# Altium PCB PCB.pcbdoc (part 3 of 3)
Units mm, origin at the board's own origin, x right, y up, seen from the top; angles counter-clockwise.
Board outline 65.2 x 64.45 mm, 2 copper layers (Top Layer, Bottom Layer); 194 components, 135 nets, 803 pads, 401 vias.
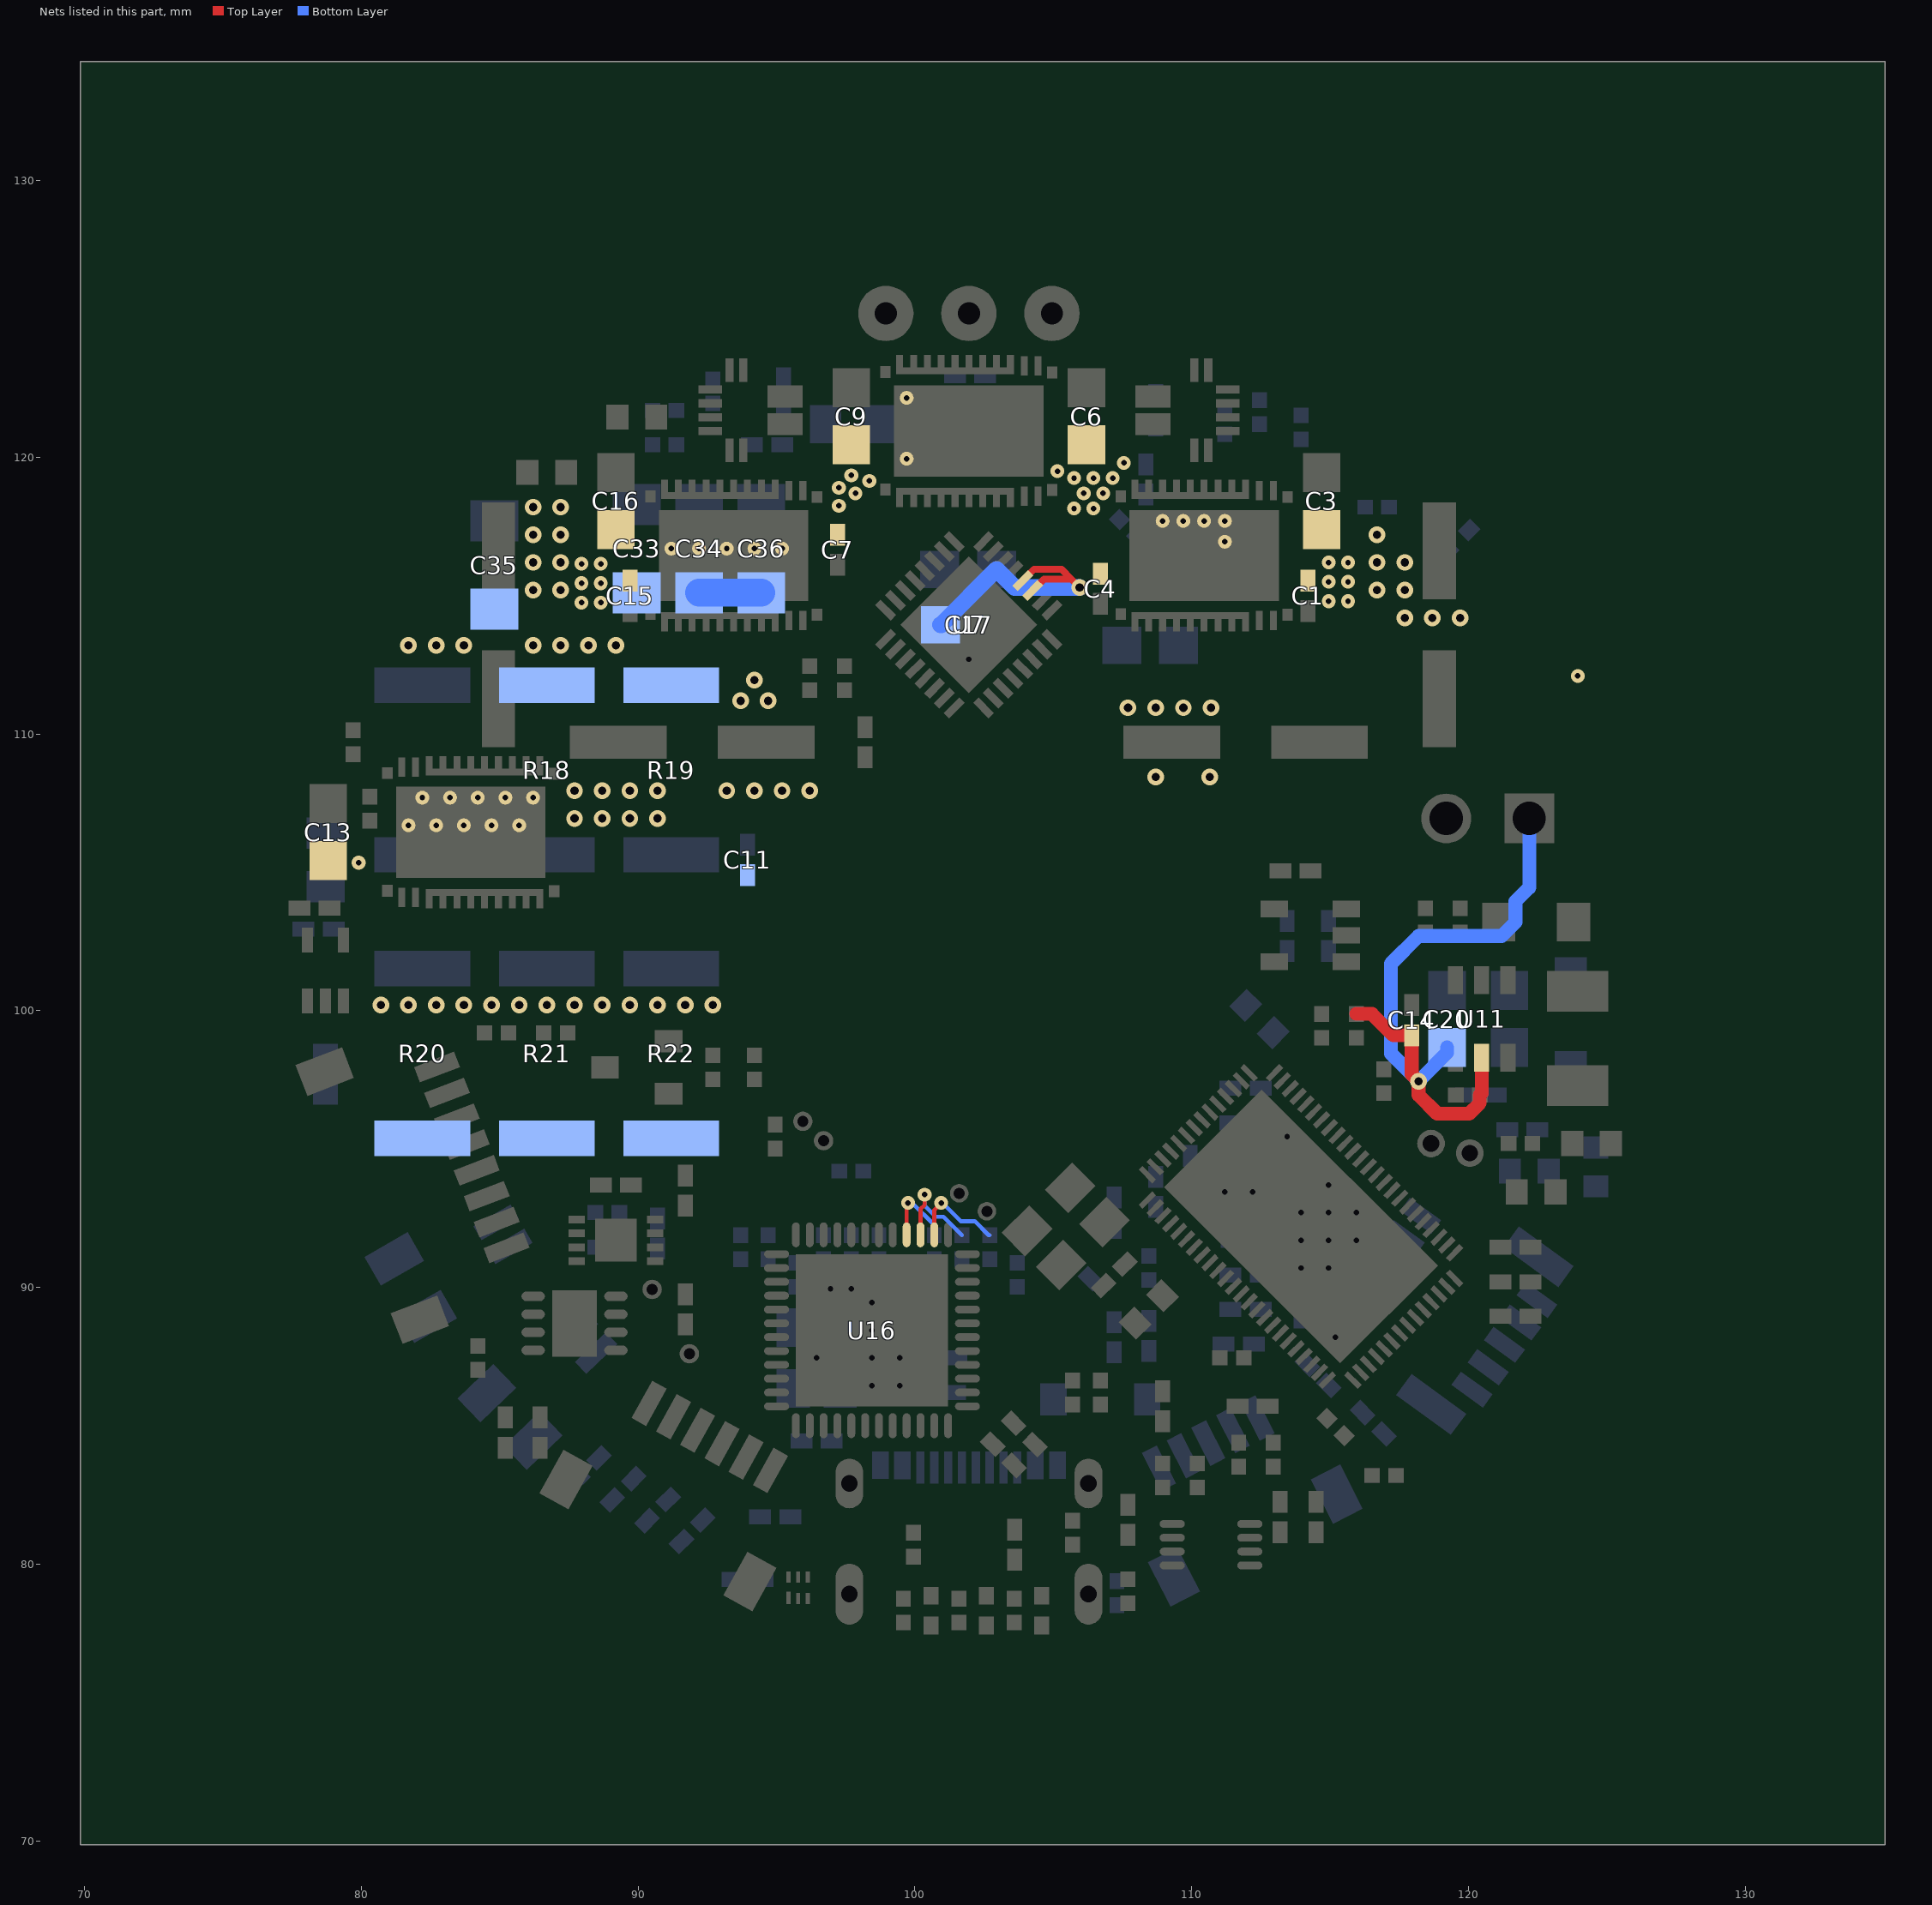
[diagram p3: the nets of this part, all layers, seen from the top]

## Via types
v1: diameter 0.5, hole 0.2, Top Layer to Bottom Layer, 297 vias
v2: diameter 0.6, hole 0.3, Top Layer to Bottom Layer, 104 vias

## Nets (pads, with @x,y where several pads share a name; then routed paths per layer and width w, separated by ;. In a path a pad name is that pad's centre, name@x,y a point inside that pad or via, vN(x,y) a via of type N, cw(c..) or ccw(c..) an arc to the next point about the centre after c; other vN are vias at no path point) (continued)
V: C1.1 C3.1 C4.1 C6.1 C7.1 C9.1 C11.1 C13.1 C14.1 C15.1 C16.1 C17.1 C20.1 C33.1 C34.1 C35.1 C36.1 pad.1@81.7,106.7 pad.1@82.2,107.7 pad.1@82.7,106.7 pad.1@83.2,107.7 pad.1@83.7,106.7 pad.1@84.2,107.7 pad.1@84.7,106.7 pad.1@85.2,107.7 pad.1@85.7,106.7 pad.1@86.2,107.7 pad.1@91.2,116.7 pad.1@92.2,116.7 pad.1@93.2,116.7 pad.1@94.2,116.7 pad.1@95.2,116.7 pad.1@99.7,119.95 pad.1@99.7,122.15 pad.1@108.95,117.7 pad.1@109.7,117.7 pad.1@110.45,117.7 pad.1@111.2,116.95 pad.1@111.2,117.7 R18.1 R19.1 R20.1 R21.1 R22.1 U7.3 U7.4 U11.5 | length 36.7
  Top Layer w0.25: U7.4@103.895,115.541 104.304,115.95 105.3,115.95 105.65,115.6 ; U7.3@104.248,115.187 104.661,115.6 105.65,115.6 ; v2(105.95,115.3) 105.65,115.6
  Top Layer w0.5: 115.95,99.883 116.517,99.883 117.29,99.11 C14.1@117.95,99.11 117.95,97.7 v2(118.2,97.45) 118.2,96.95 118.872,96.278 120.028,96.278 120.412,96.662 120.412,96.95 120.48,97.017 U11.5@120.48,98.3
  Bottom Layer w0.5: C20.1@119.23,98.67 119.23,98.48 v2(118.2,97.45) 117.2,98.45 117.2,101.7 118.2,102.7 121.2,102.7 121.7,103.2 121.7,103.95 122.2,104.45 122.2,106.95
  Bottom Layer w0.6: C17.1@100.92,113.95 100.95,113.95 102.95,115.95 103.6,115.3 v2(105.95,115.3)
  Bottom Layer w1: C34.1@92.2,115.107 C36.1@94.45,115.107
  other v1: 79.9,105.35 123.95,112.1 87.95,114.75 88.65,114.75 114.95,114.8 115.65,114.8 87.95,115.45 88.65,115.45 114.95,115.5 115.65,115.5 87.95,116.15 88.65,116.15 114.95,116.2 115.65,116.2 105.75,118.15 106.45,118.15 97.25,118.25 97.85,118.7 106.1,118.7 106.8,118.7 97.25,118.9 98.35,119.15 105.75,119.25 106.45,119.25 107.15,119.25 97.7,119.35 105.15,119.5 107.55,119.8
  other v2: 80.7,100.2 81.7,100.2 82.7,100.2 83.7,100.2 84.7,100.2 85.7,100.2 86.7,100.2 87.7,100.2 88.7,100.2 89.7,100.2 90.7,100.2 91.7,100.2 92.7,100.2 87.7,106.95 88.7,106.95 89.7,106.95 90.7,106.95 87.7,107.95 88.7,107.95 89.7,107.95 90.7,107.95 93.2,107.95 94.2,107.95 95.2,107.95 96.2,107.95 108.7,108.45 110.65,108.45 107.7,110.95 108.7,110.95 109.7,110.95 110.7,110.95 93.7,111.2 94.7,111.2 94.2,111.95 81.7,113.2 82.7,113.2 83.7,113.2 86.2,113.2 87.2,113.2 88.2,113.2 89.2,113.2 117.7,114.2 118.7,114.2 119.7,114.2 86.2,115.2 87.2,115.2 116.7,115.2 117.7,115.2 86.2,116.2 87.2,116.2 116.7,116.2 117.7,116.2 86.2,117.2 87.2,117.2 116.7,117.2 86.2,118.2 87.2,118.2
VDS_0: U16.38 | length 3.5
  Top Layer w0.15: U16.38@100.7,91.899 100.7,92.8 v1(100.95,93.05)
  Bottom Layer w0.15: v1@100.95,92.95 v1(100.95,93.05) ; v1@101,93.05 101.657,92.393 102.157,92.393 102.667,91.883 102.7,91.883
VDS_18: U16.39 | length 3.7
  Top Layer w0.15: U16.39@100.2,91.899 100.2,92.825 100.35,92.975 v1(100.35,93.35)
  Bottom Layer w0.15: v1(100.35,93.35) 100.35,92.95 100.75,92.55 101.033,92.55 101.7,91.883
VDS_75: U16.40 | length 2.8
  Top Layer w0.15: U16.40@99.7,91.899 99.7,93 v1(99.75,93.05)
  Bottom Layer w0.15: v1(99.75,93.05) 99.9,93.05 100.7,92.25 100.7,91.883
"": 
pads on no net: C1.2 C2.2 C3.2 C4.2 C5.2 C6.2 C7.2 C8.2 C9.2 C10.2 C11.2 C12.2 C13.2 C14.2 C15.2 C16.2 C17.2 C18.2 C19.2 C20.2 C21.2 C22.2 C23.2 C24.2 C25.1 C26.1 C27.1 C28.1 C29.1 C30.2 C31.2 C32.2 C33.2 C34.2 C35.2 C36.2 C37.2 C38.2 C39.2 C40.2 C41.2 C42.2 C43.2 C44.2 C45.2 C46.2 C47.2 C48.2 C49.2 C50.2 C51.2 C52.2 C53.2 C54.2 C55.2 C56.2 C57.2 C58.2 C59.2 C60.2 C61.2 C62.2 C63.2 C64.2 C65.2 C66.2 C67.2 C68.2 C69.2 C70.2 C71.2 C72.2 C73.2 C74.2 C75.2 C76.2 C77.2 C78.2 C79.2 C80.2 C81.2 C82.2 C83.2 C84.2 C85.2 C86.2 C87.2 C88.2 C89.2 C90.2 C91.2 CAN.2 D1.2 D2.2 ENC.1 GRE.1 L1.2 LED1.2 LED2.2 LED3.2 LED4.1 Q1.2 R1.2 R2.2 R3.2 R4.2 R5.2 R6.2 R7.2 R8.2 R9.2 R10.2 R11.2 R12.2 R13.2 R14.2 R15.2 R16.2 R17.2 R18.2 R19.2 R20.2 R21.2 R22.2 R23.2 R24.2 R25.2 R26.2 R27.2 R28.2 R29.2 R30.2 R31.2 R32.2 R33.2 R34.2 R35.2 R36.2 R37.2 R38.2 R39.2 R40.2 R41.2 R42.2 R43.2 R44.2 R45.2 R46.2 R47.2 R48.2 R49.2 R50.2 R51.2 R52.2 R53.2 R54.2 R55.2 R56.2 R57.2 R58.2 R59.2 R60.2 R61.2 R62.2 R63.2 R64.2 R65.2 R66.2 R67.2 RS485.2 RTMI.1 RTMI.11 SPI.1 U1.21 U1.23 U1.24 U1.25 U1.26 U1.27 U2.21 U2.23 U2.24 U2.25 U2.26 U2.27 U3.21 U3.23 U3.24 U3.25 U3.26 U3.27 U4.12 U5.2 U5.21 U5.23 U5.24 U5.25 U5.26 U5.27 U6.1 U6.10 U6.11 U6.25 U6.26 U6.27 U6.28 U6.29 U6.30 U6.36 U6.37 U6.38 U6.48 U6.49 U6.56 U6.57 U6.58 U6.64 U6.65 U6.66 U6.67 U6.68 U6.69 U6.70 U6.71 U6.74 U7.33 U8.12 U9.1 U10.1 U10.5 U11.3 U13.5 U14.1 U15.1 U17.1 U18.6 USB.2 USB.3 USB.9 X1.1 X2.1

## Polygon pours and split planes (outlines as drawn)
V on Bottom Layer (solid, pour order 2): 114.7,114.55 115.9,114.55 115.9,116.45 114.7,116.45
GND on Top Layer (solid, pour order 3): 107.8,105.25 112.85,105.25 112.85,106.85 107.8,106.85
BR on Bottom Layer (solid, remove dead copper, pour order 4): 79.95,100.95 93.2,100.95 93.2,106.45 79.95,106.45
BR on Top Layer (solid, remove dead copper, pour order 5): 80.2,102.2 93.45,102.2 93.45,104.45 80.2,104.45
GND on Mid-Layer 1 (solid, remove dead copper, pour order 7): 76.7,105.7 127.7,105.7 127.7,127.2 76.7,127.2
V on Top Layer (solid, remove dead copper, pour order 15): 107.2,107.95 111.2,107.95 111.2,111.45 107.2,111.45
GND on Top Layer (solid, remove dead copper, pour order 17): 76.2,99.7 79.7,99.7 79.7,103.95 76.2,103.95
V on Top Layer (solid, remove dead copper, pour order 18): 76.2,99.7 97.2,99.7 97.2,107.2 76.2,107.2
V on Bottom Layer (solid, remove dead copper, pour order 19): 80.2,94.7 92.95,94.7 92.95,100.45 80.2,100.45
V on Bottom Layer (solid, remove dead copper, pour order 20): 79.95,110.45 93.2,110.45 93.2,116.45 79.95,116.45
GND on Top Layer (solid, remove dead copper, pour order 21): 76.2,105.7 128.7,105.7 128.7,127.95 76.2,127.95
GND on Bottom Layer (solid, remove dead copper, pour order 22): 76.2,105.7 128.7,105.7 128.7,127.95 76.2,127.95
V on Bottom Layer (solid, remove dead copper, pour order 23): 76.2,94.7 101.7,94.7 101.7,105.7 76.2,105.7
GND on Mid-Layer 1 (solid, pour order 24): 76.7,99.7 95.95,99.7 95.95,106.2 76.7,106.2
V on Bottom Layer (solid): 96.95,119.2 96.95,117.95 97.2,117.7 98.7,119.2 98.7,119.45 97.95,119.45 97.7,119.7 97.45,119.7
V on Bottom Layer (solid, pour order 1): 104.2,118.95 104.95,119.7 107.072,119.7 107.104,119.669 107.2,119.765 107.2,120.2 107.7,120.2 107.7,120.187 107.965,119.922 107.965,118.297 107.851,118.184 107.434,118.184 106.95,117.7 105.45,117.7 104.963,118.187 104.963,118.815 104.335,118.815
V on Mid-Layer 2 (solid, remove dead copper, pour order 6): 76.2,99.45 101.95,99.45 101.95,105.7 128.7,105.7 128.7,127.95 76.2,127.95
$3N73172 on Top Layer (solid, remove dead copper, pour order 8): 94.7,120.7 93.45,119.45 90.7,119.45 90.7,118.45 95.2,118.45 95.2,119.7 95.95,120.45 95.95,121.45 94.7,121.45
C on Top Layer (solid, remove dead copper, pour order 9): 94.7,121.95 94.7,123.95 97.45,126.7 100.2,126.7 100.2,124.7 97.45,121.95
B on Top Layer (solid, remove dead copper, pour order 10): 99.2,122.95 99.2,123.7 100.2,124.7 100.2,126.7 103.7,126.7 103.7,122.95
A on Top Layer (solid, remove dead copper, pour order 11): 109.2,121.95 109.2,123.2 105.7,126.7 103.7,126.7 103.7,122.95 106.95,122.95 107.95,121.95
$3N68599 on Top Layer (solid, remove dead copper, pour order 12): 107.95,121.45 107.95,118.45 112.2,118.45 112.2,119.45 110.45,119.45 109.2,120.7 109.2,121.45
V on Top Layer (solid, remove dead copper, pour order 13): 99.2,122.7 104.7,122.7 104.7,122.2 105.45,121.45 106.95,121.45 106.95,118.95 107.7,118.2 119.45,118.2 119.45,114.95 107.45,114.95 106.95,115.45 106.45,115.45 106.2,115.2 104.7,115.2 104.2,114.7 103.45,115.45 105.45,117.45 105.45,118.7 104.95,119.2 99.2,119.2 97.45,117.45 97.45,116.7 96.95,116.7 96.2,115.95 96.2,114.95 89.45,114.95 87.7,113.2 79.2,113.2 79.2,118.45 95.2,118.45 95.2,119.7 96.95,121.45 99.2,121.45
V on Top Layer (solid, remove dead copper, pour order 14): 119.45,114.95 120.7,113.7 120.7,105.7 127.2,105.7 127.2,118.2 119.45,118.2
V on Top Layer (solid, remove dead copper, pour order 16): 79.45,108.45 79.45,105.7 80.2,104.95 86.95,104.95 88.2,106.2 91.95,106.2 92.95,107.2 96.2,107.2 96.95,107.95 96.95,109.95 95.95,110.95 95.7,110.95 94.45,112.2 93.95,112.2 92.7,110.95 92.7,109.7 91.45,108.45
GND on Mid-Layer 2 (solid, remove dead copper, pour order 25): 97.2,76.45 97.2,77.622 97.2,77.623 98.502,77.623 98.575,77.55 99.686,78.661 103.824,78.661 105.551,80.389 105.551,80.639 108.418,80.639 110.222,78.834 110.222,76.472 110.2,76.45
3.3V on Mid-Layer 2 (solid, remove dead copper, pour order 26): 128.7,105.45 101.7,105.45 95.45,99.2 76.45,99.2 76.2,98.95 76.2,76.45 128.7,76.45
GND on Mid-Layer 1 (solid, remove dead copper, pour order 27): 127.7,105.45 101.7,105.45 95.7,99.45 76.45,99.45 76.45,89.2 89.45,76.2 112.45,76.2 127.7,91.45
GND on Top Layer (solid, remove dead copper, pour order 28): 127.45,105.45 101.2,105.45 95.2,99.45 76.2,99.45 76.2,91.7 91.7,76.2 112.45,76.2 127.45,91.2
GND on Bottom Layer (solid, remove dead copper, pour order 29): 127.45,105.45 107.95,105.45 98.95,96.45 98.95,94.45 76.7,94.45 76.45,94.2 76.45,91.2 91.45,76.2 112.45,76.2 127.45,91.2

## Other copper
Top Layer:
  drawing of 395 lines, arcs and shapes, not listed
Mid-Layer 1:
  pour cut-out net GND: 118.525,106.355 118.7,105.42 119.7,105.42 119.875,106.355
  pour cut-out net M_EN: 109.665,99.163 109.925,99.275 109.925,99.425 109.665,99.538
  pour cut-out net CSPC: 93.516,121.399 93.253,121.504 93.146,121.397 93.251,121.134
  pour cut-out net M_EN: 115.837,97.015 115.725,97.275 115.575,97.275 115.462,97.015
  pour cut-out net CSPC: 93.901,123.93 93.814,123.67 93.936,123.58 94.201,123.705
  pour cut-out net SCK: 118.45,87.466 118.346,87.203 118.452,87.096 118.716,87.201
  pour cut-out net ENC_I: 111.549,80.434 111.654,80.698 111.547,80.804 111.284,80.7
  pour cut-out net ENC_B: 111.099,81.934 111.204,82.198 111.097,82.304 110.834,82.2
  pour cut-out net ENC_B: 111.115,86.262 111.375,86.169 111.375,86.381 111.115,86.638
  pour cut-out net ENC_A: 110.135,81.138 109.95,81.025 109.95,80.875 110.135,80.763
  pour cut-out net ENC_A: 110.162,85.985 110.275,85.725 110.425,85.725 110.537,85.985
  pour cut-out net F_CS: 113.738,84.453 113.995,84.374 114.078,84.503 113.941,84.768
  pour cut-out net FA: 125.701,101.18 125.666,100.881 125.794,100.786 126.001,100.955
  pour cut-out net FC: 126.162,100.486 126.271,100.225 126.421,100.225 126.537,100.484
  pour cut-out net M_MISO/MODE: 104.219,93.513 103.955,93.508 103.927,93.346 104.155,93.144
  pour cut-out net M_MOSI/IDRIVE: 104.416,90.35 104.253,90.353 104.147,90.247 104.15,90.084
  pour cut-out net M_MOSI/IDRIVE: 103.165,90.113 103.425,90.225 103.425,90.375 103.165,90.488
  pour cut-out net M_CS: 94.751,93.966 94.646,93.703 94.753,93.596 95.016,93.701
  pour cut-out net MOSI_2: 102.562,87.035 102.675,86.775 102.825,86.775 102.937,87.035
  pour cut-out net MISO_2: 103.2,86.716 103.136,86.492 103.242,86.386 103.466,86.45
  pour cut-out net F_CS: 107.165,81.763 107.425,81.875 107.425,82.025 107.165,82.138
  pour cut-out net SCK: 105.383,78.848 105.119,78.962 105.005,78.864 105.1,78.602
  pour cut-out net CS_2: 90.515,83.863 90.775,83.975 90.775,84.125 90.515,84.238
  pour cut-out net MOSI_2: 91.365,83.363 91.625,83.475 91.625,83.625 91.365,83.738
  pour cut-out net MISO_2: 92.215,82.863 92.475,82.975 92.475,83.125 92.215,83.238
  pour cut-out net SCK_2: 93.065,82.363 93.325,82.475 93.325,82.625 93.065,82.738
  pour cut-out net FA: 105.1,77.816 105.047,77.603 105.153,77.497 105.366,77.55
Mid-Layer 2:
  pour cut-out net NRST: 92.199,87.578 92.324,87.968 92.218,88.074 91.828,87.949
  pour cut-out net FA: 122.058,112.238 121.966,112.513 121.816,112.534 121.687,112.289
  pour cut-out net FC: 122.715,112.287 122.552,112.529 122.401,112.51 122.343,112.241
  pour cut-out net CSNC: 91.865,122.263 92.125,122.375 92.125,122.525 91.865,122.638
  pour cut-out net CSNA: 113.449,120.784 113.503,120.997 113.397,121.103 113.184,121.049
  pour cut-out net CSPA: 110.649,122.234 110.754,122.497 110.647,122.604 110.384,122.499
  pour cut-out net FA: 110.416,121.399 110.152,121.504 110.046,121.397 110.15,121.134
  pour cut-out net BRAKE: 78.9,99.249 79.139,99.375 79.108,99.525 78.825,99.617
  pour cut-out net CSPC: 120.197,92.046 120.412,92.306 120.379,92.485 120.128,92.415
  pour cut-out net F_EN: 108.1,92.016 107.996,91.753 108.103,91.646 108.366,91.751
  pour cut-out net GR_GND: 87.513,97.785 87.575,97.525 87.825,97.525 87.888,97.785
  pour cut-out net GR_GND: 86.95,94.184 87.089,94.412 86.912,94.589 86.684,94.45
  pour cut-out net F_STATUS: 119,89.016 119.013,88.869 119.119,88.763 119.266,88.751
  pour cut-out net MOSI: 118.35,88.116 118.324,87.93 118.43,87.824 118.616,87.851
  pour cut-out net 5V: 109.937,82.215 109.825,82.4 109.675,82.4 109.562,82.215
  pour cut-out net 5V: 109.999,82.034 110.104,82.298 109.997,82.404 109.734,82.3
  pour cut-out net 5V: 112.05,82.966 111.946,82.703 112.052,82.596 112.316,82.701
  pour cut-out net TX: 93.573,86.856 93.347,86.725 93.413,86.575 93.723,86.512
  pour cut-out net FA: 105.1,79.298 105.005,79.037 105.119,78.938 105.383,79.052
  pour cut-out net F_STATUS: 105.965,84.213 106.211,84.325 106.211,84.475 105.965,84.588
  pour cut-out net MOSI: 98.883,79.148 98.619,79.262 98.505,79.164 98.6,78.902
  pour cut-out net MISO: 98.817,79.352 99.081,79.238 99.195,79.337 99.1,79.598
  pour cut-out net SCK: 104.7,89.448 104.605,89.186 104.719,89.088 104.983,89.202
  pour cut-out net MOSI: 105.285,88.738 105.025,88.625 105.025,88.475 105.285,88.363
  pour cut-out net SCK: 96.938,79.622 97.083,79.888 97.004,80.021 96.748,79.945
  pour cut-out net NRST: 93.285,88.338 93.025,88.225 93.025,88.075 93.285,87.963
  pour cut-out net DE: 89.882,88.459 90.147,88.322 90.276,88.405 90.197,88.662
  pour cut-out net RX: 90.028,87.518 90.148,87.268 90.298,87.282 90.402,87.552
  pour cut-out net TX: 90.684,86.95 90.947,86.846 91.054,86.953 90.95,87.216
  pour cut-out net 5V: 107.684,84.2 107.947,84.096 108.054,84.203 107.95,84.466
  pour cut-out net F_EN: 102.887,88.365 102.775,88.625 102.625,88.625 102.512,88.365
  pour cut-out net FC: 96.513,78.785 96.625,78.525 96.775,78.525 96.888,78.785
  pour cut-out net CUR_SENSE_FAULT: 95.937,80.315 95.825,80.575 95.675,80.575 95.562,80.315
  pour cut-out net FA: 105.366,78.049 105.102,78.154 104.996,78.047 105.1,77.784
Bottom Layer:
  pour cut-out net B: 101.735,124.223 102.29,123.343 102.79,123.708 102.946,125.109
  pour cut-out net 5V: 119.056,95.492 118.95,95.745 118.45,95.745 118.31,95.567
  pour cut-out net $3N68599: 108.95,118.45 108.95,118.95 108.62,119.05 108.62,118.26
  pour cut-out net $3N40773: 106.39,113.275 106.39,113.025 106.765,112.712 106.765,113.587
  pour cut-out net B: 102.29,123.97 102.145,123.22 102.935,123.22 102.79,123.97
  pour cut-out net $3N52263: 101.2,122.382 101.7,122.382 101.845,122.68 101.055,122.68
  pour cut-out net $3N52263: 101.536,121.943 102.066,120.511 103.181,121.889 101.767,122.419
  pour cut-out net $3N73172: 93.86,120.04 94.36,120.04 94.505,120.18 93.715,120.18
  pour cut-out net $3N53370: 96.018,120.7 95.595,120.72 95.595,120.18 96.018,120.2
  pour cut-out net $3N53370: 95.841,120.627 96.194,120.273 97.316,120.511 96.201,121.889
  pour cut-out net 5V: 107.988,117.725 107.882,117.875 107.469,118.062 107.575,117.537
  pour cut-out net AGPI_A: 108.418,116.838 108.392,117.13 108.02,116.758 108.312,116.732
  pour cut-out net 5V: 110.555,121.575 110.93,121.417 110.93,121.983 110.555,121.825
  pour cut-out net 5V: 111.7,121.575 111.7,121.825 111.47,121.983 111.47,121.417
  pour cut-out net FA: 110.716,120.959 110.716,120.709 110.93,120.552 110.93,121.117
  pour cut-out net 5V: 92.041,121.575 92.041,121.825 91.666,121.97 91.666,121.43
  pour cut-out net CSNC: 90.642,121.055 90.8,121.43 90.234,121.43 90.392,121.055
  pour cut-out net CSNC: 90.392,122.017 90.234,121.97 90.8,121.97 90.642,122.017
  pour cut-out net CSNC: 90.642,121.095 90.392,121.095 90.234,120.72 90.8,120.72
  pour cut-out net CSNA: 113.084,121.941 113.084,122.191 112.72,122.348 112.72,121.783
  pour cut-out net 5V: 109.695,122.495 108.97,122.64 108.97,121.85 109.695,121.995
  pour cut-out net 5V: 94.86,122.01 94.86,121.51 94.98,121.365 94.98,122.155
  pour cut-out net V: 122.45,105.3 123.075,106.05 121.325,106.05 121.95,105.3
  pour cut-out net GND: 118.525,106.355 118.7,105.42 119.7,105.42 119.875,106.355
  pour cut-out net BR: 80.14,103.2 79.39,103.22 79.39,102.68 80.14,102.7
  pour cut-out net $4N2455: 77.655,103.689 77.51,103.22 78.3,103.22 78.155,103.689
  pour cut-out net $4N2455: 77.728,103.865 78.082,103.512 79.389,103.918 78.011,105.033
  pour cut-out net V: 118.024,97.628 118.538,97.435 119.905,97.965 118.555,99.042
  pour cut-out net $5N859: 121.862,97.435 122.377,97.627 122.155,98.733 120.805,97.965
  pour cut-out net $5N869: 122.302,99.495 122.685,99.819 122.155,101.233 120.888,100.025
  pour cut-out net $5N859: 122.908,97.627 123.262,97.273 124.275,97.59 123.125,97.59
  pour cut-out net 5V: 115.97,102.405 115.22,102.55 115.22,101.76 115.97,101.905
  pour cut-out net DBGSPI_MISO: 119.394,86.862 119.305,86.739 119.385,86.472 119.665,86.857
  pour cut-out net DBGSPI_MOSI: 119.961,87.575 119.852,87.425 120.034,87.238 120.323,87.763
  pour cut-out net DBGSPI_SCK: 120.361,88.125 120.495,87.975 120.978,87.788 120.722,88.313
  pour cut-out net DBGSPI_TRG: 117.992,90.968 118.142,91.001 118.074,91.133 117.804,91.329
  pour cut-out net 3.3V: 121.541,89.687 121.747,89.537 122.23,89.35 121.857,89.875
  pour cut-out net MISO: 96.017,90.092 95.97,90.28 95.97,89.755 96.017,89.942
  pour cut-out net M_MISO/MODE: 95.205,91.092 95.205,90.942 95.43,90.755 95.43,91.166
  pour cut-out net MODE_0: 94.775,92.391 94.625,92.391 94.438,92.166 94.962,92.166
  pour cut-out net M_MISO/MODE: 94.205,91.092 94.205,90.942 94.43,90.755 94.43,91.28
  pour cut-out net M_MISO/MODE: 95.195,91.092 94.97,91.28 94.97,90.755 95.195,90.942
  pour cut-out net M_MOSI/IDRIVE: 99.205,90.942 99.43,90.755 99.43,91.166 99.205,91.092
  pour cut-out net IDRIVE_0: 98.625,92.391 98.438,92.166 98.962,92.166 98.775,92.391
  pour cut-out net M_MOSI/IDRIVE: 98.205,90.942 98.43,90.755 98.43,91.28 98.205,91.092
  pour cut-out net M_MOSI/IDRIVE: 99.195,90.942 99.195,91.092 98.97,91.28 98.97,90.755
  pour cut-out net IDRIVE_18: 97.775,92.387 97.625,92.387 97.438,92.166 97.963,92.166
  pour cut-out net M_MOSI/IDRIVE: 98.195,90.942 98.195,91.092 97.97,91.28 97.97,90.755
  pour cut-out net M_MOSI/IDRIVE: 97.205,90.942 97.43,90.755 97.43,91.28 97.205,91.092
  pour cut-out net MODE_45: 94.118,92.325 93.906,92.325 93.43,92.166 93.97,91.912
  pour cut-out net M_MISO/MODE: 93.625,90.509 93.775,90.509 93.962,90.734 93.438,90.734
  pour cut-out net M_MISO/MODE: 94.195,91.092 93.97,91.28 93.97,90.755 94.195,90.942
  pour cut-out net IDRIVE_75: 97.129,92.206 97.036,92.325 96.612,92.166 96.97,91.782
  pour cut-out net M_MOSI/IDRIVE: 97.195,90.942 97.195,91.092 96.97,91.28 96.97,90.755
  pour cut-out net VDS_0: 102.271,92.173 102.43,91.749 102.756,92.166 102.331,92.325
  pour cut-out net M_SCK/VDS: 102.205,90.942 102.43,90.755 102.43,91.28 102.205,91.092
  pour cut-out net M_SCK/VDS: 103.129,91.418 102.746,91.3 102.97,90.734 103.129,91.206
  pour cut-out net M_SCK/VDS: 102.195,90.942 102.195,91.092 101.97,91.28 101.97,90.755
  pour cut-out net M_SCK/VDS: 101.205,90.942 101.43,90.755 101.43,91.28 101.205,91.092
  pour cut-out net V: 94.45,114.607 94.45,115.607 93.064,115.85 93.064,114.365
  pour cut-out net V: 92.2,114.607 93.586,114.365 93.586,115.85 92.2,115.607
  pour cut-out net M_CS: 96.759,94.275 96.759,94.125 96.984,93.938 96.984,94.462
  pour cut-out net M_CS/NC: 98.633,94.291 98.634,94.444 98.092,94.47 98.416,94.034
  pour cut-out net $1N28894: 103.125,82.687 103.275,82.687 103.35,82.912 103.05,82.912
  pour cut-out net $1N27790: 102.775,82.687 102.85,82.912 102.55,82.912 102.625,82.687
  pour cut-out net $1N27790: 102.775,84.288 102.625,84.288 102.55,84.063 102.85,84.063
  pour cut-out net $1N27747: 102.125,84.288 102.05,84.063 102.35,84.063 102.275,84.288
  pour cut-out net $1N27790: 101.775,82.687 101.85,82.912 101.55,82.912 101.625,82.687
  pour cut-out net $1N27747: 101.125,84.288 101.05,84.063 101.35,84.063 101.275,84.288
  pour cut-out net $6N7492: 109.415,95.103 109.68,94.35 110.174,95.14 109.467,95.405
  pour cut-out net F_EN: 108.525,91.641 108.375,91.641 108.188,91.416 108.713,91.416
  pour cut-out net $6N8440: 110.745,89.429 111.01,88.93 111.01,89.47 110.792,89.735
  pour cut-out net $6N8522: 110.745,95.183 111.01,94.476 111.8,94.97 111.047,95.235
  pour cut-out net 5V: 119.547,96.415 120.3,96.68 119.51,97.174 119.245,96.467
  pour cut-out net 5V: 120.924,96.004 121.01,95.476 121.8,95.97 121.101,96.181
  pour cut-out net 3.3V: 116.297,86.053 116.091,85.941 116.377,85.655 116.403,85.947
  pour cut-out net 3.3V: 115.559,86.275 115.582,86.425 115.169,86.613 115.146,86.088
  pour cut-out net 3.3V: 112.758,87.415 112.905,87.621 112.64,88.22 112.64,87.68
  pour cut-out net 3.3V: 114.025,88.3 114.213,88.51 113.688,88.51 113.875,88.3
  pour cut-out net 3.3V: 110.635,90.575 110.635,90.325 111.01,90.18 111.01,90.72
  pour cut-out net 3.3V: 111.575,91.095 111.325,91.095 111.013,90.72 111.8,90.72
  pour cut-out net 3.3V: 111.575,91.055 111.845,91.43 111.055,91.43 111.325,91.055
  pour cut-out net 3.3V: 108.165,94.353 108.43,93.6 108.924,94.39 108.333,94.538
  pour cut-out net 3.3V: 107.075,94 106.93,93.64 107.47,93.64 107.325,94
  pour cut-out net 3.3V: 110.635,97.325 110.635,97.075 111.01,96.93 111.01,97.47
  pour cut-out net $1N6064: 89.191,92.095 89.033,91.72 89.598,91.72 89.441,92.095
  pour cut-out net $1N6016: 87.792,91.575 87.792,91.325 88.167,91.18 88.167,91.72
  pour cut-out net $1N6033: 87.902,92.329 88.092,92.165 88.733,92.43 88.167,92.43
  pour cut-out net $1N6064: 90.055,92.37 90.43,92.1 90.43,92.89 90.055,92.62
  pour cut-out net $6N18292: 116.592,83.695 116.442,83.695 116.255,83.47 116.78,83.47
  pour cut-out net ENC_A_5: 107.375,79.8 107.225,79.8 107.037,79.666 107.562,79.666
  pour cut-out net 3.3V: 123.273,93.473 123.627,93.827 123.3,94.65 123.3,93.75
  pour cut-out net 3.3V: 123.45,93.4 124.15,93.25 124.15,94.05 123.45,93.9
  pour cut-out net 3.3V: 113.877,98.627 113.546,99.24 112.91,98.604 113.523,98.273
  pour cut-out net 5V: 79.9,98.15 79.9,98.65 79.15,98.8 79.15,98
  pour cut-out net 3.3V: 101.57,86.955 101.758,87.18 101.233,87.18 101.42,86.955
  pour cut-out net 3.3V: 107.955,88.67 108.18,88.483 108.18,89.008 107.955,88.82
  pour cut-out net 3.3V: 106.705,88.67 106.93,88.483 106.93,89.008 106.705,88.82
  pour cut-out net 3.3V: 107.695,88.67 107.695,88.82 107.47,89.008 107.47,88.483
  pour cut-out net 3.3V: 91.585,82.26 91.585,82.41 91.382,82.598 91.205,82.073
  pour cut-out net 3.3V: 90.682,82.632 90.709,82.341 91.08,82.712 90.788,82.738
  pour cut-out net 3.3V: 91.932,81.882 91.959,81.591 92.33,81.962 92.038,81.988
  pour cut-out net 3.3V: 92.815,81.51 92.815,81.66 92.632,81.848 92.455,81.323
  pour cut-out net 3.3V: 89.085,83.76 89.085,83.91 88.882,84.098 88.497,83.365
  pour cut-out net 3.3V: 89.152,84.146 89.046,84.252 88.754,84.225 89.056,83.924
  pour cut-out net 3.3V: 89.432,83.382 89.459,83.091 89.83,83.462 89.538,83.488
  pour cut-out net 3.3V: 90.335,83.01 90.335,83.16 90.132,83.348 89.955,82.823
  pour cut-out net VDS_75: 100.775,92.25 100.625,92.25 100.438,92.166 100.963,92.166
  pour cut-out net M_SCK/VDS: 101.195,90.942 101.195,91.092 100.97,91.28 100.97,90.755
  pour cut-out net 5V: 108.467,85.15 108.655,85.375 108.13,85.375 108.317,85.15
  pour cut-out net OSC_OUT: 95.98,85.425 96.167,85.65 95.642,85.65 95.83,85.425
  pour cut-out net OSC_OUT: 94.922,87.209 94.841,87.078 95,86.654 95.346,87.05
  pour cut-out net OSC_IN: 96.547,89.409 96.541,89.203 96.7,88.779 96.971,89.25
  pour cut-out net OSC_IN: 98.125,88.852 98.125,89.002 97.9,89.19 97.9,88.665
  pour cut-out net OSC_OUT: 95.98,84.945 95.83,84.945 95.642,84.72 96.167,84.72
  pour cut-out net $1N42270: 118.716,116.982 118.85,116.577 119.3,117.027 118.895,117.162
  pour cut-out net $1N42270: 117.677,118.073 117.677,118.327 117.416,118.47 117.416,117.93
  pour cut-out net ENC_I_5: 110.874,85.623 110.758,85.527 111.11,84.91 111.209,85.553
  pour cut-out net ENC_B_5: 110.875,83.418 111.025,83.495 111.212,83.815 110.687,83.548
  pour cut-out net $6N18292: 110.094,82.993 110.228,83.061 110.293,83.346 109.825,83.108
  pour cut-out net ENC_A_5: 108.319,83.307 108.391,83.166 108.639,83.15 108.389,83.641
  pour cut-out net $1N32304: 86.966,87.758 87.071,87.65 87.36,87.674 87.02,88.025
  pour cut-out net $1N32059: 87.661,87.038 87.765,86.93 88.054,86.955 87.715,87.306
  pour cut-out net $1N6033: 85.804,92.325 86.004,92.575 85.448,92.888 84.345,91.699
  pour cut-out net $1N6016: 85.638,91.075 86.071,91.325 86.17,91.638 84.845,90.833
  pour cut-out net 3.3V: 94.57,79.895 94.42,79.895 94.233,79.72 94.758,79.72
  pour cut-out net 3.3V: 95.57,81.205 95.758,81.43 95.233,81.43 95.42,81.205
  pour cut-out net INLA: 110.987,105.365 110.875,105.625 110.725,105.625 110.612,105.365
  pour cut-out net INLA: 110.434,105.95 110.697,105.846 110.804,105.953 110.7,106.216
  pour cut-out net INLB: 111.337,106.365 111.225,106.625 111.075,106.625 110.962,106.365
  pour cut-out net INLB: 110.684,106.95 110.947,106.846 111.054,106.953 110.949,107.216
  pour cut-out net INLC: 111.587,107.365 111.475,107.625 111.325,107.625 111.212,107.365
  pour cut-out net INLC: 111.212,108.035 111.325,107.775 111.475,107.775 111.587,108.035
  pour cut-out net FA: 121.707,111.895 121.926,111.681 122.088,111.721 122.072,111.984
  pour cut-out net FC: 122.585,111.852 122.86,111.798 122.943,111.924 122.791,112.166
  pour cut-out net CSNC: 91.535,122.638 91.275,122.575 91.275,122.325 91.535,122.263
  pour cut-out net CSNA: 113.387,120.965 113.325,121.225 113.075,121.225 113.012,120.965
  pour cut-out net 5V: 109.509,122.088 109.57,121.955 109.82,121.955 109.884,122.081
  pour cut-out net FA: 110.384,120.9 110.612,120.761 110.789,120.938 110.649,121.166
  pour cut-out net 5V: 94.266,121.399 94.038,121.539 93.861,121.362 94.001,121.134
  pour cut-out net FC: 93.516,122.499 93.288,122.639 93.111,122.462 93.251,122.234
  pour cut-out net $3N40772: 106.3,113.834 106.439,114.062 106.262,114.239 106.034,114.099
  pour cut-out net $3N40773: 106.365,112.962 106.625,113.025 106.625,113.275 106.365,113.337
  pour cut-out net M_FAULT: 98.187,113.276 98.45,113.172 98.556,113.278 98.452,113.541
  pour cut-out net M_CS/NC: 99.866,111.017 100.118,111.135 100.107,111.285 99.839,111.391
  pour cut-out net M_SCK/VDS: 99.2,111.184 99.304,111.447 99.197,111.554 98.934,111.45
  pour cut-out net 3.3V: 110.334,96.95 110.562,96.811 110.739,96.988 110.599,97.216
  pour cut-out net 3.3V: 110.515,97.013 110.775,97.075 110.775,97.325 110.515,97.388
  pour cut-out net $6N8522: 109.662,96.585 109.725,96.325 109.975,96.325 110.037,96.585
  pour cut-out net AGPI_A: 115.485,98.488 115.225,98.375 115.225,98.225 115.485,98.113
  pour cut-out net AGPI_A: 118.822,94.165 118.571,94.235 118.538,94.056 118.753,93.796
  pour cut-out net AGPI_A: 117.784,94.651 118.047,94.546 118.154,94.653 118.049,94.916
  pour cut-out net ADC_VM: 118.685,93.488 118.425,93.375 118.425,93.225 118.685,93.113
  pour cut-out net ADC_VM: 115.284,100.15 115.547,100.046 115.654,100.153 115.549,100.416
  pour cut-out net $6N7492: 108.815,95.213 109.075,95.275 109.075,95.525 108.815,95.588
  pour cut-out net 3.3V: 107.4,94.466 107.261,94.238 107.438,94.061 107.666,94.201
  pour cut-out net 3.3V: 107.815,94.263 108.075,94.325 108.075,94.575 107.815,94.638
  pour cut-out net F_EN: 108.244,91.773 108.375,91.547 108.525,91.613 108.588,91.923
  pour cut-out net 3.3V: 105.112,91.885 105.225,91.625 105.375,91.625 105.487,91.885
  pour cut-out net 3.3V: 105.934,89.2 106.113,89.181 106.219,89.287 106.2,89.466
  pour cut-out net 3.3V: 110.45,90.184 110.538,90.362 110.362,90.538 110.184,90.45
  pour cut-out net $6N8440: 110.634,89.451 110.862,89.311 111.039,89.488 110.899,89.716
  pour cut-out net 3.3V: 113.016,87.6 112.788,87.739 112.611,87.562 112.75,87.334
  pour cut-out net 3.3V: 113.249,87.334 113.354,87.598 113.247,87.704 112.984,87.6
  pour cut-out net 3.3V: 120.065,89.113 120.325,89.225 120.325,89.375 120.065,89.488
  pour cut-out net $1N6033: 87.115,92.012 87.375,92.075 87.375,92.325 87.115,92.387
  pour cut-out net $1N6033: 86.966,92.45 86.788,92.538 86.612,92.362 86.7,92.184
  pour cut-out net $1N6016: 86.785,91.388 86.525,91.325 86.525,91.075 86.785,91.013
  pour cut-out net $1N6016: 87.2,91.184 87.288,91.362 87.112,91.538 86.934,91.45
  pour cut-out net DBGSPI_MISO: 119.184,86.7 119.447,86.596 119.554,86.703 119.45,86.966
  pour cut-out net DBGSPI_MOSI: 119.715,87.313 119.975,87.425 119.975,87.575 119.715,87.688
  pour cut-out net DBGSPI_SCK: 120.115,87.863 120.375,87.975 120.375,88.125 120.115,88.238
  pour cut-out net DBGSPI_CS: 120.45,88.684 120.503,88.897 120.397,89.003 120.184,88.95
  pour cut-out net 3.3V: 116.45,86.366 116.346,86.103 116.452,85.996 116.716,86.101
  pour cut-out net 3.3V: 116.535,86.538 116.275,86.425 116.275,86.275 116.535,86.163
  pour cut-out net ENC_A_5: 107.45,80.216 107.346,79.953 107.453,79.846 107.716,79.95
  pour cut-out net ENC_A_5: 107.888,80.365 107.775,80.625 107.625,80.625 107.513,80.365
  pour cut-out net ENC_I_5: 109.755,85.456 110.078,85.505 110.16,85.655 109.935,85.785
  pour cut-out net ENC_B_5: 111.137,83.365 111.025,83.625 110.875,83.625 110.762,83.365
  pour cut-out net ENC_I: 111.716,86.95 111.503,87.003 111.397,86.897 111.45,86.684
  pour cut-out net 3.3V: 113.6,81.716 113.496,81.453 113.602,81.346 113.866,81.451
  pour cut-out net 3.3V: 110.384,79.951 110.597,79.897 110.703,80.003 110.649,80.216
  pour cut-out net $6N18292: 116.321,83.702 116.442,83.461 116.592,83.596 116.6,83.953
  pour cut-out net $6N18292: 116.185,84.138 115.925,84.025 115.925,83.875 116.185,83.763
  pour cut-out net 5V: 109.5,82.066 109.396,81.803 109.502,81.696 109.766,81.801
  pour cut-out net 5V: 117.763,84.285 117.875,84.025 118.025,84.025 118.138,84.285
  pour cut-out net CAN_RX: 90.865,93.262 91.125,93.375 91.125,93.525 90.865,93.637
  pour cut-out net GR_D5: 92.221,90.65 92.17,90.496 92.276,90.39 92.38,90.31
  pour cut-out net CAN_TX: 92.388,91.365 92.275,91.625 92.125,91.625 92.013,91.365
  pour cut-out net CAN_RX: 96.035,94.887 95.775,94.775 95.775,94.625 96.035,94.512
  pour cut-out net FC: 126.581,100.745 126.548,101.031 126.405,101.081 126.227,100.868
  pour cut-out net SCK: 98.765,78.063 99.025,78.175 99.025,78.325 98.765,78.438
  pour cut-out net F_CS: 99.315,81.113 99.575,81.225 99.575,81.375 99.315,81.488
  pour cut-out net MODE_0: 97.151,93.116 97.17,92.976 97.276,92.87 97.416,92.851
  pour cut-out net M_MISO/MODE: 104.6,93.305 104.7,93.561 104.584,93.659 104.314,93.547
  pour cut-out net M_MISO/MODE: 93.966,89.75 93.753,89.803 93.647,89.697 93.701,89.484
  pour cut-out net M_MOSI/IDRIVE: 104.416,90.35 104.25,90.356 104.144,90.25 104.15,90.084
  pour cut-out net SCK: 104.785,89.637 104.525,89.525 104.525,89.375 104.785,89.262
  pour cut-out net MOSI: 105.285,88.738 105.025,88.625 105.025,88.475 105.285,88.363
  pour cut-out net M_FAULT: 103.484,88.501 103.747,88.396 103.854,88.503 103.75,88.766
  pour cut-out net OSC_IN: 93.7,88.799 93.939,88.925 93.908,89.075 93.625,89.167
  pour cut-out net OSC_OUT: 93.963,88.335 94.075,88.075 94.225,88.075 94.338,88.335
  pour cut-out net F_CS: 106.75,81.966 106.646,81.703 106.753,81.596 107.016,81.701
  pour cut-out net SCK: 105.1,78.616 104.996,78.353 105.103,78.246 105.366,78.351
  pour cut-out net $1N27790: 106.785,84.588 106.675,84.475 106.675,84.325 106.785,84.213
  pour cut-out net $1N28894: 103.388,82.615 103.275,82.875 103.125,82.875 103.013,82.615
  pour cut-out net $1N32304: 85.034,87.35 85.297,87.246 85.404,87.352 85.299,87.616
  pour cut-out net $1N32059: 86.638,86.365 86.525,86.45 86.375,86.45 86.263,86.365
  pour cut-out net $1N32059: 86.638,86.365 86.731,86.625 86.519,86.625 86.263,86.365
  pour cut-out net $1N32059: 86.638,86.365 86.731,86.625 86.519,86.625 86.263,86.365
  pour cut-out net 3.3V: 89.201,84.566 89.096,84.303 89.203,84.196 89.466,84.301
  pour cut-out net 3.3V: 102.115,80.512 102.375,80.625 102.375,80.775 102.115,80.887
  pour cut-out net 3.3V: 101.785,80.887 101.525,80.775 101.525,80.625 101.785,80.512
  pour cut-out net 3.3V: 102.785,80.887 102.525,80.775 102.525,80.625 102.785,80.512
  pour cut-out net 3.3V: 101.2,80.434 101.253,80.647 101.147,80.753 100.934,80.7
  pour cut-out net 3.3V: 93.216,81.45 92.953,81.554 92.846,81.447 92.95,81.184
  pour cut-out net 5V: 121.009,117.019 120.783,117.16 120.603,116.98 120.744,116.754
  pour cut-out net 5V: 107.95,84.434 108.054,84.697 107.947,84.804 107.684,84.7
  pour cut-out net 3.3V: 94.85,80.516 94.746,80.252 94.852,80.146 95.116,80.25
  pour cut-out net 3.3V: 95.349,80.484 95.453,80.747 95.347,80.854 95.084,80.749

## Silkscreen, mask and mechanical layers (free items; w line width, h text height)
Top Overlay:
  text "B" at 102.665,125.811 h0.65
  text "C" at 99.643,125.762 h0.65
  text "A" at 105.905,125.49 h0.65
  text "-" at 118.2,109.279 h0.98
  text "+" at 122.2,109.279 h0.98
  text "+" at 84.462,98.762 h0.65 r201
  text "D0" at 84.325,97.314 h0.65 r21
  text "+" at 95.456,96.461 h0.65
  text "D1" at 84.697,96.346 h0.65 r21
  text "D2" at 85.033,95.397 h0.65 r21
  text "+" at 117.519,95.197 h0.65
  text "D3" at 85.414,94.483 h0.65 r21
  text "B0" at 96.87,94.195 h0.65
  text "T" at 119.572,93.657 h0.65
  text "D4" at 85.776,93.528 h0.65 r21
  text "CK" at 100.154,93.459 h0.65
  text "IO" at 101.897,93.181 h0.65
  text "D5" at 86.126,92.586 h0.65 r21
  text "-" at 86.753,91.431 h0.65 r21
  text "-" at 89.469,89.876 h0.65
  text "R" at 90.731,87.417 h0.65
  text "+" at 90.81,87.14 h0.65 r330
  text "CS" at 91.894,86.088 h0.65 r60
  text "MO" at 92.744,85.588 h0.65 r60
  text "MI" at 93.644,85.088 h0.65 r60
  text "CK" at 94.494,84.538 h0.65 r60
  text "-" at 95.26,84.06 h0.65 r60
Bottom Overlay:
  text "EXTERMINATE" at 106.067,110.582 h1.14
  text "L" at 85.2,93.17 h0.65
  text "H" at 86.7,90.67 h0.65
  text "A" at 88.2,88.92 h0.65
  text "B" at 89.7,87.42 h0.65
  text "-" at 111.892,86.094 h0.65
  text "I" at 110.925,85.741 h0.65
  text "B" at 110.449,85.485 h0.65
  text "+" at 109.444,84.993 h0.65
  text "A" at 108.407,84.405 h0.65
Mechanical 1:
  circle w0.1: c101.95,101.7 r25
  circle w0.025: c101.95,101.7 r7.45
  circle w0.025: c104.84,82.593 r0.325
  circle w0.025: c99.06,82.593 r0.325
